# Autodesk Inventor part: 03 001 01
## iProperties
Shininess: 64.0
Length Units: 11269
Angle Units: 11279
Time Units: 11290
Mass Units: 11283
Length Display Precision: 3
Angle Display Precision: 2
Compacted: True
Part Number: 03 001 01
Document SubType Name: Modeling
Created: 2003-12
Material: Standard
Designer: HAH
Manufacturer: Standard
Standards Organization: Custom
Description: Boden
Density: 0.0
Volumn: 0.0
Area: 0.0
PropertySet Name: Model Information
Control State: 0
Master: False
Checked Out: False
Author: HAH
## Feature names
1. Extrusion1
